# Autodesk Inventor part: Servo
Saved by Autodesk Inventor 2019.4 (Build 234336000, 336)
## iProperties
Created: 2020-04
Part Number: Servo
Material: Generic
Document SubType Name: Modeling
Designer: Administrator
Density: 1 g/cm^3
Appearance: Default
Title: Servo v14
Author: Administrator
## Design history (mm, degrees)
feature "Body1"
body "Solid1"
